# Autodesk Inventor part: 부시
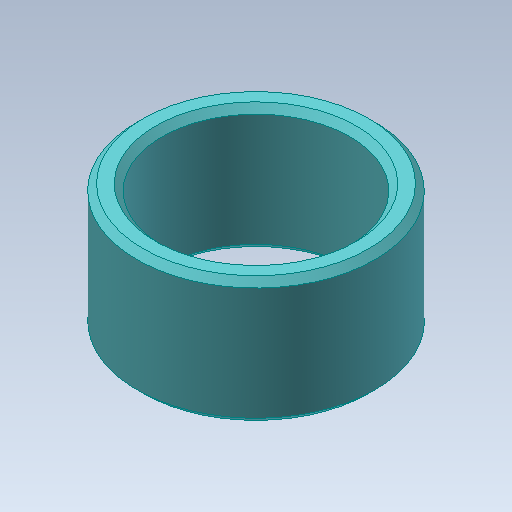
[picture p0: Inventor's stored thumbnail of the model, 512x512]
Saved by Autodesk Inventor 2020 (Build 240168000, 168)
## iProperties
Created: 2013-01
Part Number: 부시
Document SubType Name: Modeling
Designer: mdu
Density: 1 g/cm^3
Material: 강철, 연강
Appearance: 하늘색 중간
Author: mdu
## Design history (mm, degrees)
sketch "스케치1"
  geometry: L1 (15, 20)-(15, -46) reference; L2 (-20, 19)-(20, 19); L3 (30.7, -1)-(-30.7, -1) reference; L4 (19, 19)-(19, -1); L5 (15, -1)-(19, -1); L6 (0, 0)-(0, 19); L7 (19, 19)-(15, 19)
  constraints: 12 end point, 6 point on line, 1 collinear, 1 midpoint, 1 perpendicular, 1 vertical, 2 other
  dimensions: "d0" = 38 diameter of L4 L6; "d5" = 20 distance between parallel lines of L2 L3
revolve "회전1" sketch "스케치1" stored, may be unused: angle "d1" = 90 deg
chamfer "모따기1" distance "d2" = 1; stored, may be unused: second distance "d3" = 2, angle "d4" = 45 deg
node "솔리드1"
node "참조2"
